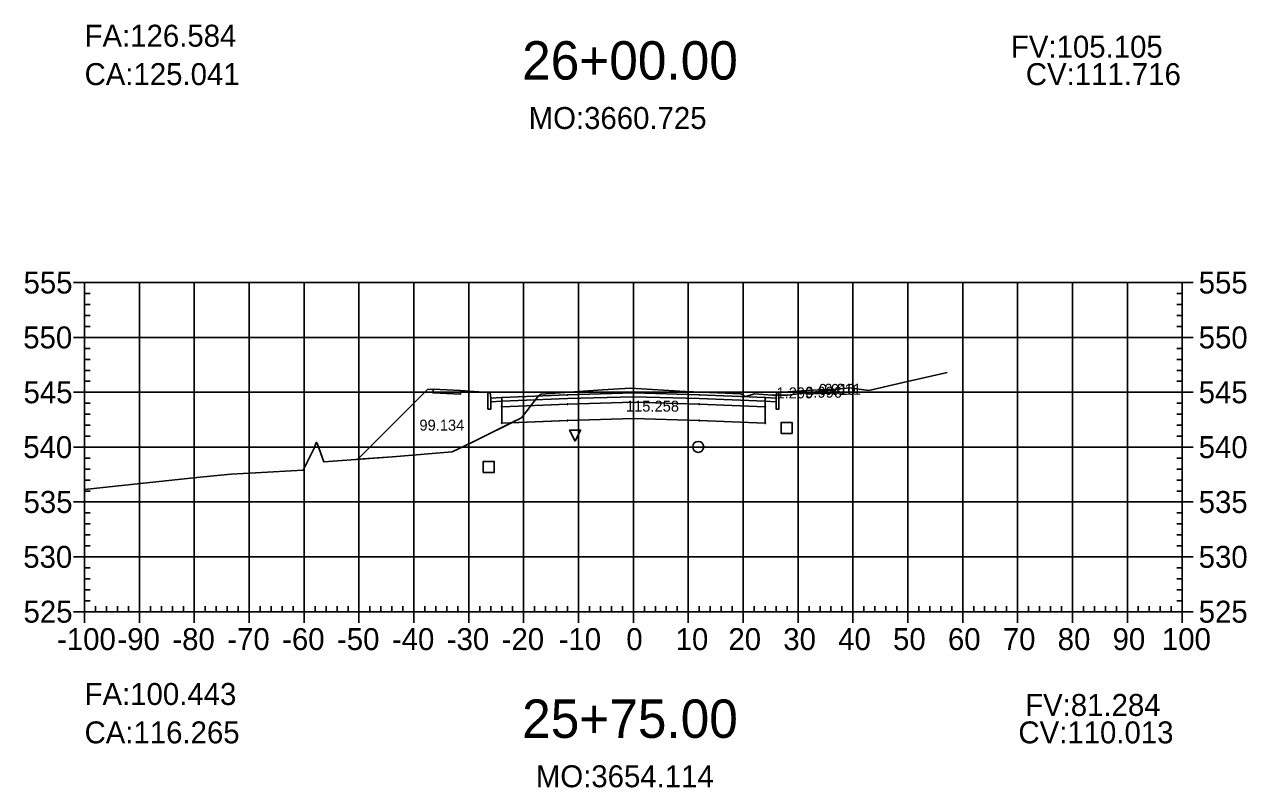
# Model space of a CAD drawing. Extents: x 704834 to 709892, y 372981 to 377533.
# Drawn here: x 706025.9 to 706248.6, y 373610.8 to 373749.9 of the extents above; entities that cross this region are included whole.
import ezdxf

# ---------------------------------------------------------------- set-up
doc = ezdxf.new("R2010")
doc.units = 0
for name, color, linetype in [('1', 7, 'Continuous'), ('10', 7, 'Continuous'), ('13', 7, 'Continuous'), ('14', 7, 'Continuous'), ('4', 7, 'Continuous'), ('57', 7, 'Continuous'), ('59', 7, 'Continuous'), ('Default_Xsect', 7, 'Continuous'), ('Existing', 7, 'Continuous')]:
    doc.layers.add(name, color=color, linetype=linetype)

msp = doc.modelspace()

# ---------------------------------------------------------------- linework, layer by layer
for points in [[(706099.37, 373683.33), (706086.64, 373670.6)], [(706100.37, 373683.37), (706099.37, 373683.33)], [(706110.37, 373682.77), (706105.37, 373683.17)], [(706163.37, 373682.77), (706168.37, 373683.17)], [(706173.37, 373683.37), (706174.37, 373683.33)], [(706174.37, 373683.33), (706174.46, 373683.42)]]:
    msp.add_lwpolyline(points)
for points in [[(706105.37, 373683.17), (706100.37, 373683.37), (706100.37, 373682.7), (706105.37, 373682.5)], [(706110.87, 373681.77), (706110.79, 373682.77), (706110.37, 373682.77), (706110.37, 373679.77), (706110.87, 373679.77)], [(706112.87, 373681.85), (706110.87, 373681.77), (706110.87, 373681.1), (706112.87, 373681.18)], [(706136.87, 373682.02), (706148.87, 373681.66), (706160.87, 373681.18), (706160.87, 373681.85), (706148.87, 373682.33), (706136.87, 373682.69), (706124.87, 373682.33), (706112.87, 373681.85), (706112.87, 373681.18), (706124.87, 373681.66)], [(706136.87, 373681.02), (706148.87, 373680.66), (706160.87, 373680.18), (706160.87, 373681.18), (706148.87, 373681.66), (706136.87, 373682.02), (706124.87, 373681.66), (706112.87, 373681.18), (706112.87, 373680.18), (706124.87, 373680.66)], [(706136.82, 373681.97), (706136.92, 373681.97), (706136.92, 373682.07), (706136.82, 373682.07)], [(706160.87, 373681.18), (706162.87, 373681.1), (706162.87, 373681.77), (706160.87, 373681.85)], [(706162.87, 373679.77), (706163.37, 373679.77), (706163.37, 373682.77), (706162.96, 373682.77), (706162.87, 373681.77)], [(706168.37, 373682.5), (706173.37, 373682.7), (706173.37, 373683.37), (706168.37, 373683.17)], [(706112.82, 373680.13), (706112.92, 373680.13), (706112.92, 373680.23), (706112.82, 373680.23)], [(706136.87, 373678.02), (706148.87, 373677.66), (706160.87, 373677.18), (706160.87, 373680.18), (706148.87, 373680.66), (706136.87, 373681.02), (706124.87, 373680.66), (706112.87, 373680.18), (706112.87, 373677.18), (706124.87, 373677.66)], [(706124.82, 373680.61), (706124.92, 373680.61), (706124.92, 373680.71), (706124.82, 373680.71)], [(706136.82, 373680.97), (706136.92, 373680.97), (706136.92, 373681.07), (706136.82, 373681.07)], [(706148.82, 373680.61), (706148.92, 373680.61), (706148.92, 373680.71), (706148.82, 373680.71)], [(706160.82, 373680.13), (706160.92, 373680.13), (706160.92, 373680.23), (706160.82, 373680.23)], [(706124.82, 373677.61), (706124.92, 373677.61), (706124.92, 373677.71), (706124.82, 373677.71)], [(706136.82, 373677.97), (706136.92, 373677.97), (706136.92, 373678.07), (706136.82, 373678.07)], [(706148.82, 373677.61), (706148.92, 373677.61), (706148.92, 373677.71), (706148.82, 373677.71)], [(706112.82, 373677.13), (706112.92, 373677.13), (706112.92, 373677.23), (706112.82, 373677.23)], [(706160.82, 373677.13), (706160.92, 373677.13), (706160.92, 373677.23), (706160.82, 373677.23)]]:
    msp.add_lwpolyline(points, close=True)
at = {"layer": '1'}
for points in [[(706086.64, 373670.6), (706092.97, 373671.07), (706103.85, 373671.99), (706107.46, 373673.69), (706114.6, 373677.25), (706112.87, 373677.18), (706112.87, 373680.18), (706112.87, 373681.18), (706110.87, 373681.1), (706110.87, 373679.77), (706110.37, 373679.77), (706110.37, 373682.77), (706105.37, 373683.17), (706105.37, 373682.5), (706100.37, 373682.7), (706100.37, 373683.37), (706099.37, 373683.33)], [(706114.6, 373677.25), (706116.48, 373678.19), (706119.55, 373682.17), (706120.04, 373682.48), (706131.25, 373683.28), (706136.36, 373683.59), (706146.34, 373682.97), (706156.44, 373682.53), (706157.21, 373682.07), (706157.37, 373682.03), (706158.74, 373682.45), (706158.91, 373682.52), (706162.17, 373682.29), (706163.37, 373682.3), (706163.37, 373679.77), (706162.87, 373679.77), (706162.87, 373681.1), (706160.87, 373681.18), (706160.87, 373680.18), (706160.87, 373677.18), (706148.87, 373677.66), (706136.87, 373678.02), (706124.87, 373677.66)], [(706163.37, 373682.3), (706164.97, 373682.32), (706168.37, 373682.71), (706168.37, 373683.17), (706163.37, 373682.77)], [(706168.37, 373682.71), (706173.37, 373683.29), (706173.37, 373682.7), (706168.37, 373682.5)], [(706173.37, 373683.29), (706173.88, 373683.35), (706173.37, 373683.37)], [(706173.88, 373683.35), (706174.46, 373683.42), (706174.37, 373683.33)], [(706126.24, 373673.92), (706125.24, 373675.92), (706127.24, 373675.92)]]:
    msp.add_lwpolyline(points, close=True, dxfattribs=at)
at = {"layer": '10'}
msp.add_lwpolyline([(706109.51, 373668.21), (706111.51, 373668.21), (706111.51, 373670.21), (706109.51, 373670.21)], close=True, dxfattribs=at)
at = {"layer": '13'}
msp.add_circle((706148.68, 373672.87), 1, dxfattribs=at)
at = {"layer": '14'}
for points in [[(706112.87, 373681.85), (706112.87, 373681.9), (706112.87, 373681.85), (706112.82, 373681.85), (706112.87, 373681.85), (706112.87, 373681.8), (706112.87, 373681.85), (706112.92, 373681.85)], [(706124.87, 373682.33), (706124.87, 373682.38), (706124.87, 373682.33), (706124.82, 373682.33), (706124.87, 373682.33), (706124.87, 373682.28), (706124.87, 373682.33), (706124.92, 373682.33)], [(706136.87, 373682.69), (706136.87, 373682.74), (706136.87, 373682.69), (706136.82, 373682.69), (706136.87, 373682.69), (706136.87, 373682.64), (706136.87, 373682.69), (706136.92, 373682.69)], [(706148.87, 373682.33), (706148.87, 373682.38), (706148.87, 373682.33), (706148.82, 373682.33), (706148.87, 373682.33), (706148.87, 373682.28), (706148.87, 373682.33), (706148.92, 373682.33)], [(706160.87, 373681.85), (706160.87, 373681.9), (706160.87, 373681.85), (706160.82, 373681.85), (706160.87, 373681.85), (706160.87, 373681.8), (706160.87, 373681.85), (706160.92, 373681.85)], [(706174.46, 373683.42), (706174.46, 373683.47), (706174.46, 373683.42), (706174.41, 373683.42), (706174.46, 373683.42), (706174.46, 373683.37), (706174.46, 373683.42), (706174.51, 373683.42)], [(706174.46, 373683.42), (706174.46, 373683.47), (706174.46, 373683.42), (706174.41, 373683.42), (706174.46, 373683.42), (706174.46, 373683.37), (706174.46, 373683.42), (706174.51, 373683.42)], [(706086.64, 373670.6), (706086.64, 373670.65), (706086.64, 373670.6), (706086.59, 373670.6), (706086.64, 373670.6), (706086.64, 373670.55), (706086.64, 373670.6), (706086.69, 373670.6)]]:
    msp.add_lwpolyline(points, dxfattribs=at)
at = {"layer": '4'}
msp.add_lwpolyline([(706163.77, 373675.32), (706165.77, 373675.32), (706165.77, 373677.32), (706163.77, 373677.32)], close=True, dxfattribs=at)
at = {"layer": '57'}
for p, q in [((706034.87, 373702.82), (706036.87, 373702.82)), ((706036.87, 373702.82), (706236.87, 373702.82)), ((706036.87, 373642.82), (706036.87, 373702.82)), ((706036.87, 373642.82), (706036.87, 373702.82)), ((706046.87, 373642.82), (706046.87, 373702.82)), ((706056.87, 373642.82), (706056.87, 373702.82)), ((706066.87, 373642.82), (706066.87, 373702.82)), ((706076.87, 373642.82), (706076.87, 373702.82)), ((706086.87, 373642.82), (706086.87, 373702.82)), ((706096.87, 373642.82), (706096.87, 373702.82)), ((706106.87, 373642.82), (706106.87, 373702.82)), ((706116.87, 373642.82), (706116.87, 373702.82)), ((706126.87, 373642.82), (706126.87, 373702.82)), ((706136.87, 373642.82), (706136.87, 373702.82)), ((706146.87, 373642.82), (706146.87, 373702.82)), ((706156.87, 373642.82), (706156.87, 373702.82)), ((706166.87, 373642.82), (706166.87, 373702.82)), ((706176.87, 373642.82), (706176.87, 373702.82)), ((706186.87, 373642.82), (706186.87, 373702.82)), ((706196.87, 373642.82), (706196.87, 373702.82)), ((706206.87, 373642.82), (706206.87, 373702.82)), ((706216.87, 373642.82), (706216.87, 373702.82)), ((706226.87, 373642.82), (706226.87, 373702.82)), ((706236.87, 373642.82), (706236.87, 373702.82)), ((706236.87, 373642.82), (706236.87, 373702.82)), ((706238.87, 373702.82), (706236.87, 373702.82)), ((706036.87, 373700.82), (706037.87, 373700.82)), ((706236.87, 373700.82), (706235.87, 373700.82)), ((706036.87, 373698.82), (706037.87, 373698.82)), ((706236.87, 373698.82), (706235.87, 373698.82)), ((706036.87, 373696.82), (706037.87, 373696.82)), ((706236.87, 373696.82), (706235.87, 373696.82)), ((706036.87, 373694.82), (706037.87, 373694.82)), ((706236.87, 373694.82), (706235.87, 373694.82)), ((706034.87, 373692.82), (706036.87, 373692.82)), ((706036.87, 373692.82), (706236.87, 373692.82)), ((706036.87, 373690.82), (706037.87, 373690.82)), ((706236.87, 373690.82), (706235.87, 373690.82)), ((706238.87, 373692.82), (706236.87, 373692.82)), ((706036.87, 373688.82), (706037.87, 373688.82)), ((706236.87, 373688.82), (706235.87, 373688.82)), ((706036.87, 373686.82), (706037.87, 373686.82)), ((706236.87, 373686.82), (706235.87, 373686.82)), ((706036.87, 373684.82), (706037.87, 373684.82)), ((706236.87, 373684.82), (706235.87, 373684.82)), ((706034.87, 373682.82), (706036.87, 373682.82)), ((706036.87, 373682.82), (706236.87, 373682.82)), ((706238.87, 373682.82), (706236.87, 373682.82)), ((706036.87, 373680.82), (706037.87, 373680.82)), ((706236.87, 373680.82), (706235.87, 373680.82)), ((706036.87, 373678.82), (706037.87, 373678.82)), ((706236.87, 373678.82), (706235.87, 373678.82)), ((706036.87, 373676.82), (706037.87, 373676.82)), ((706236.87, 373676.82), (706235.87, 373676.82)), ((706034.87, 373672.82), (706036.87, 373672.82)), ((706036.87, 373674.82), (706037.87, 373674.82)), ((706036.87, 373672.82), (706236.87, 373672.82)), ((706236.87, 373674.82), (706235.87, 373674.82)), ((706238.87, 373672.82), (706236.87, 373672.82)), ((706036.87, 373670.82), (706037.87, 373670.82)), ((706236.87, 373670.82), (706235.87, 373670.82)), ((706036.87, 373668.82), (706037.87, 373668.82)), ((706236.87, 373668.82), (706235.87, 373668.82)), ((706036.87, 373666.82), (706037.87, 373666.82)), ((706236.87, 373666.82), (706235.87, 373666.82)), ((706036.87, 373664.82), (706037.87, 373664.82)), ((706236.87, 373664.82), (706235.87, 373664.82)), ((706034.87, 373662.82), (706036.87, 373662.82)), ((706036.87, 373662.82), (706236.87, 373662.82)), ((706238.87, 373662.82), (706236.87, 373662.82)), ((706036.87, 373660.82), (706037.87, 373660.82)), ((706236.87, 373660.82), (706235.87, 373660.82)), ((706036.87, 373658.82), (706037.87, 373658.82)), ((706236.87, 373658.82), (706235.87, 373658.82)), ((706036.87, 373656.82), (706037.87, 373656.82)), ((706236.87, 373656.82), (706235.87, 373656.82)), ((706034.87, 373652.82), (706036.87, 373652.82)), ((706036.87, 373654.82), (706037.87, 373654.82)), ((706036.87, 373652.82), (706236.87, 373652.82)), ((706236.87, 373654.82), (706235.87, 373654.82)), ((706238.87, 373652.82), (706236.87, 373652.82)), ((706036.87, 373650.82), (706037.87, 373650.82)), ((706236.87, 373650.82), (706235.87, 373650.82)), ((706036.87, 373648.82), (706037.87, 373648.82)), ((706236.87, 373648.82), (706235.87, 373648.82)), ((706036.87, 373646.82), (706037.87, 373646.82)), ((706236.87, 373646.82), (706235.87, 373646.82)), ((706036.87, 373644.82), (706037.87, 373644.82)), ((706236.87, 373644.82), (706235.87, 373644.82)), ((706034.87, 373642.82), (706036.87, 373642.82)), ((706036.87, 373642.82), (706236.87, 373642.82)), ((706036.87, 373642.82), (706236.87, 373642.82)), ((706036.87, 373640.82), (706036.87, 373642.82)), ((706038.87, 373642.82), (706038.87, 373643.82)), ((706040.87, 373642.82), (706040.87, 373643.82)), ((706042.87, 373642.82), (706042.87, 373643.82)), ((706044.87, 373642.82), (706044.87, 373643.82)), ((706046.87, 373640.82), (706046.87, 373642.82)), ((706048.87, 373642.82), (706048.87, 373643.82)), ((706050.87, 373642.82), (706050.87, 373643.82)), ((706052.87, 373642.82), (706052.87, 373643.82)), ((706054.87, 373642.82), (706054.87, 373643.82)), ((706056.87, 373640.82), (706056.87, 373642.82)), ((706058.87, 373642.82), (706058.87, 373643.82)), ((706060.87, 373642.82), (706060.87, 373643.82)), ((706062.87, 373642.82), (706062.87, 373643.82)), ((706064.87, 373642.82), (706064.87, 373643.82)), ((706066.87, 373640.82), (706066.87, 373642.82)), ((706068.87, 373642.82), (706068.87, 373643.82)), ((706070.87, 373642.82), (706070.87, 373643.82)), ((706072.87, 373642.82), (706072.87, 373643.82)), ((706074.87, 373642.82), (706074.87, 373643.82)), ((706076.87, 373640.82), (706076.87, 373642.82)), ((706078.87, 373642.82), (706078.87, 373643.82)), ((706080.87, 373642.82), (706080.87, 373643.82)), ((706082.87, 373642.82), (706082.87, 373643.82)), ((706084.87, 373642.82), (706084.87, 373643.82)), ((706086.87, 373640.82), (706086.87, 373642.82)), ((706088.87, 373642.82), (706088.87, 373643.82)), ((706090.87, 373642.82), (706090.87, 373643.82)), ((706092.87, 373642.82), (706092.87, 373643.82)), ((706094.87, 373642.82), (706094.87, 373643.82)), ((706096.87, 373640.82), (706096.87, 373642.82)), ((706098.87, 373642.82), (706098.87, 373643.82)), ((706100.87, 373642.82), (706100.87, 373643.82)), ((706102.87, 373642.82), (706102.87, 373643.82)), ((706104.87, 373642.82), (706104.87, 373643.82)), ((706106.87, 373640.82), (706106.87, 373642.82)), ((706108.87, 373642.82), (706108.87, 373643.82)), ((706110.87, 373642.82), (706110.87, 373643.82)), ((706112.87, 373642.82), (706112.87, 373643.82)), ((706114.87, 373642.82), (706114.87, 373643.82)), ((706116.87, 373640.82), (706116.87, 373642.82)), ((706118.87, 373642.82), (706118.87, 373643.82)), ((706120.87, 373642.82), (706120.87, 373643.82)), ((706122.87, 373642.82), (706122.87, 373643.82)), ((706124.87, 373642.82), (706124.87, 373643.82)), ((706126.87, 373640.82), (706126.87, 373642.82)), ((706128.87, 373642.82), (706128.87, 373643.82)), ((706130.87, 373642.82), (706130.87, 373643.82)), ((706132.87, 373642.82), (706132.87, 373643.82)), ((706134.87, 373642.82), (706134.87, 373643.82)), ((706136.87, 373640.82), (706136.87, 373642.82)), ((706138.87, 373642.82), (706138.87, 373643.82)), ((706140.87, 373642.82), (706140.87, 373643.82)), ((706142.87, 373642.82), (706142.87, 373643.82)), ((706144.87, 373642.82), (706144.87, 373643.82)), ((706146.87, 373640.82), (706146.87, 373642.82)), ((706148.87, 373642.82), (706148.87, 373643.82)), ((706150.87, 373642.82), (706150.87, 373643.82)), ((706152.87, 373642.82), (706152.87, 373643.82)), ((706154.87, 373642.82), (706154.87, 373643.82)), ((706156.87, 373640.82), (706156.87, 373642.82)), ((706158.87, 373642.82), (706158.87, 373643.82)), ((706160.87, 373642.82), (706160.87, 373643.82)), ((706162.87, 373642.82), (706162.87, 373643.82)), ((706164.87, 373642.82), (706164.87, 373643.82)), ((706166.87, 373640.82), (706166.87, 373642.82)), ((706168.87, 373642.82), (706168.87, 373643.82)), ((706170.87, 373642.82), (706170.87, 373643.82)), ((706172.87, 373642.82), (706172.87, 373643.82)), ((706174.87, 373642.82), (706174.87, 373643.82)), ((706176.87, 373640.82), (706176.87, 373642.82)), ((706178.87, 373642.82), (706178.87, 373643.82)), ((706180.87, 373642.82), (706180.87, 373643.82)), ((706182.87, 373642.82), (706182.87, 373643.82)), ((706184.87, 373642.82), (706184.87, 373643.82)), ((706186.87, 373640.82), (706186.87, 373642.82)), ((706188.87, 373642.82), (706188.87, 373643.82)), ((706190.87, 373642.82), (706190.87, 373643.82)), ((706192.87, 373642.82), (706192.87, 373643.82)), ((706194.87, 373642.82), (706194.87, 373643.82)), ((706196.87, 373640.82), (706196.87, 373642.82)), ((706198.87, 373642.82), (706198.87, 373643.82)), ((706200.87, 373642.82), (706200.87, 373643.82)), ((706202.87, 373642.82), (706202.87, 373643.82)), ((706204.87, 373642.82), (706204.87, 373643.82)), ((706206.87, 373640.82), (706206.87, 373642.82)), ((706208.87, 373642.82), (706208.87, 373643.82)), ((706210.87, 373642.82), (706210.87, 373643.82)), ((706212.87, 373642.82), (706212.87, 373643.82)), ((706214.87, 373642.82), (706214.87, 373643.82)), ((706216.87, 373640.82), (706216.87, 373642.82)), ((706218.87, 373642.82), (706218.87, 373643.82)), ((706220.87, 373642.82), (706220.87, 373643.82)), ((706222.87, 373642.82), (706222.87, 373643.82)), ((706224.87, 373642.82), (706224.87, 373643.82)), ((706226.87, 373640.82), (706226.87, 373642.82)), ((706228.87, 373642.82), (706228.87, 373643.82)), ((706230.87, 373642.82), (706230.87, 373643.82)), ((706232.87, 373642.82), (706232.87, 373643.82)), ((706234.87, 373642.82), (706234.87, 373643.82)), ((706236.87, 373640.82), (706236.87, 373642.82)), ((706238.87, 373642.82), (706236.87, 373642.82))]:
    msp.add_line(p, q, dxfattribs=at)
at = {"layer": 'Default_Xsect'}
msp.add_lwpolyline([(706086.64, 373670.6), (706099.37, 373683.33), (706100.37, 373683.37), (706105.37, 373683.17), (706110.37, 373682.77), (706110.79, 373682.77), (706110.87, 373681.77), (706112.87, 373681.85), (706124.87, 373682.33), (706136.87, 373682.69), (706148.87, 373682.33), (706160.87, 373681.85), (706162.87, 373681.77), (706162.96, 373682.77), (706163.37, 373682.77), (706168.37, 373683.17), (706173.37, 373683.37), (706174.37, 373683.33), (706174.46, 373683.42)], dxfattribs=at)
at = {"layer": 'Existing'}
msp.add_lwpolyline([(706036.87, 373665.09), (706042.5, 373665.69), (706057.33, 373667.3), (706063.51, 373667.88), (706068.02, 373668.15), (706076.72, 373668.61), (706078.74, 373672.75), (706079.07, 373673.65), (706079.15, 373673.65), (706079.31, 373673.35), (706080.45, 373670.14), (706092.97, 373671.07), (706103.85, 373671.99), (706107.46, 373673.69), (706116.48, 373678.19), (706119.55, 373682.17), (706120.04, 373682.48), (706131.25, 373683.28), (706136.36, 373683.59), (706146.34, 373682.97), (706156.44, 373682.53), (706157.21, 373682.07), (706157.37, 373682.03), (706158.74, 373682.45), (706158.91, 373682.52), (706162.17, 373682.29), (706164.97, 373682.32), (706176.19, 373683.62), (706179.74, 373683.15), (706186.02, 373684.59), (706194.06, 373686.4)], dxfattribs=at)

# ---------------------------------------------------------------- texts
for s, p in [('CA:125.041', (706036.87, 373738.82)), ('CV:111.716', (706208.37, 373738.82)), ('CA:116.265', (706036.87, 373618.82)), ('CV:110.013', (706207.02, 373618.82))]:
    msp.add_text(s, height=4).set_placement(p)
at = {"layer": '1'}
for s, p in [('26+00.00', (706116.6, 373739.82)), ('25+75.00', (706116.6, 373619.82))]:
    msp.add_text(s, height=7, dxfattribs=at).set_placement(p)
at = {"layer": '14'}
for p in [(706100.34, 373683.32), (706100.34, 373682.65), (706105.34, 373682.45), (706168.34, 373682.45), (706173.34, 373683.32), (706173.34, 373682.65)]:
    msp.add_text('+', height=0.1, dxfattribs=at).set_placement(p)
at = {"layer": '57'}
for s, p in [('555', (706025.75, 373700.82)), ('555', (706239.87, 373700.82)), ('550', (706025.7, 373690.82)), ('550', (706239.87, 373690.82)), ('545', (706025.75, 373680.82)), ('545', (706239.87, 373680.82)), ('540', (706025.7, 373670.82)), ('540', (706239.87, 373670.82)), ('535', (706025.75, 373660.82)), ('535', (706239.87, 373660.82)), ('530', (706025.7, 373650.82)), ('530', (706239.87, 373650.82)), ('525', (706025.75, 373640.82)), ('525', (706239.87, 373640.82)), ('-100', (706031.86, 373635.82)), ('-90', (706042.87, 373635.82)), ('-80', (706052.87, 373635.82)), ('-70', (706062.87, 373635.82)), ('-60', (706072.87, 373635.82)), ('-50', (706082.87, 373635.82)), ('-40', (706092.87, 373635.82)), ('-30', (706102.87, 373635.82)), ('-20', (706112.87, 373635.82)), ('-10', (706123.26, 373635.82)), ('0', (706135.58, 373635.82)), ('10', (706144.57, 373635.82)), ('20', (706154.18, 373635.82)), ('30', (706164.18, 373635.82)), ('40', (706174.18, 373635.82)), ('50', (706184.18, 373635.82)), ('60', (706194.18, 373635.82)), ('70', (706204.18, 373635.82)), ('80', (706214.18, 373635.82)), ('90', (706224.18, 373635.82)), ('100', (706233.17, 373635.82))]:
    msp.add_text(s, height=4, dxfattribs=at).set_placement(p)
at = {"layer": '59'}
for s, height, p in [('FA:126.584', 4, (706036.87, 373745.82)), ('FV:105.105', 4, (706205.66, 373743.82)), ('MO:3660.725', 4, (706117.79, 373730.82)), ('0.010', 2, (706170.65, 373682.34)), ('0.011', 2, (706171.66, 373682.37)), ('1.299', 2, (706162.94, 373681.71)), ('0.996', 2, (706168.18, 373681.83)), ('115.258', 2, (706135.51, 373679.29)), ('99.134', 2, (706097.88, 373675.83)), ('FA:100.443', 4, (706036.87, 373625.82)), ('FV:81.284', 4, (706208.25, 373623.82)), ('MO:3654.114', 4, (706119.1, 373610.82))]:
    msp.add_text(s, height=height, dxfattribs=at).set_placement(p)

doc.saveas('drawing.dxf')
